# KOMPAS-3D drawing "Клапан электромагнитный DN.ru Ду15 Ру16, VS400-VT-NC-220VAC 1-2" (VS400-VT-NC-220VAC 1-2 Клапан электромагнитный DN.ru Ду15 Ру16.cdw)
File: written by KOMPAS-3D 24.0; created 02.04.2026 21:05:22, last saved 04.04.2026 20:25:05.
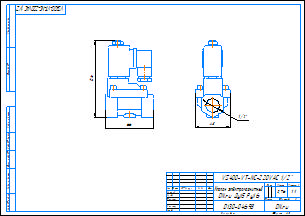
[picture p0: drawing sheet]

Document properties: c3d_UniqueCompID: ef56311e-7521-43dc-8291-0e6108b3d81d; Обозначение: VS400-ET-NC-220VAC 1-2; Наименование: Клапан электромагнитный DN.ru Ду15 Ру16; Автор: artio; Класс точности: c; Знак неуказанной шероховатости: Шероховатость не задана; Рассекать на разрезах: Да; c3d_UniqueCompID: ef56311e-7521-43dc-8291-0e6108b3d81d; Обозначение: VS400-ET-NC-220VAC 3-8; Наименование: Клапан электромагнитный DN.ru Ду10 Ру16; Автор: artio; Класс точности: c; Знак неуказанной шероховатости: Шероховатость не задана; Рассекать на разрезах: Да; Автор: artio; Форматы листов документа: A3; Полное имя файла: VS400-VT-NC-220VAC 1-2 Клапан электромагнитный DN.ru Ду15 Ру16.m3d; Масса: 0.759; Наименование: Клапан электромагнитный DN.ru Ду15 Ру16; Количество листов документа: 1; Примечание: D130-04698

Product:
- Body: Тело 1  | qty 1
    Масса: 1.030062
- Part/product: Клапан электромагнитный DN.ru Ду15 Ру16  | designation VS400-VT-NC-220VAC 1-2
    Масса: 0.759
    Раздел спецификации: Прочие изделия
    Примечание: D130-04698
    additional columns: ef56311e-7521-43dc-8291-0e6108b3d81d; VS400-ET-NC-220VAC 1-2; artio; c; Шероховатость не задана; Да

Views: Вид 1, Спереди, Проекционный вид 2
Referenced files in C:\Users\artio\OneDrive\Рабочий стол\Клапан электромагнитный DN.ru VS4x-xT-NC-x\DN10\: VS400-ET-NC-220VAC 3-8 Клапан электромагнитный DN.ru Ду10 Ру16.m3d, VS400-ET-NC-220VAC 3-8 Клапан электромагнитный DN.ru Ду10 Ру16.cdw
Referenced files in C:\Users\artio\OneDrive\Рабочий стол\Клапан электромагнитный DN.ru\VS400-VT-NC\VS400-VT-NC-220VAC\: VS400-VT-NC-220VAC 1-2 Клапан электромагнитный DN.ru Ду15 Ру16.m3d
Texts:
  VS400-VT-NC-220VAC 1-2
  Линейный размер
  Клапан электромагнитный
  DN.ru Ду15 Ру16
  VS400-VT-NC-220VAC 1/2"
  VS400-VT-NC-220VAC 1/2"-
  Клапан электромагнитный DN.ru Ду15 Ру16
  VS400-VT-NC-220VAC 1-2 Клапан электромагнитный DN.ru Ду15 Ру16
Dimensions and other numbers on the sheet: 0; 3; 2; 4; 48; 1/2"; 66; 106; 1:1; 1; 0,76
